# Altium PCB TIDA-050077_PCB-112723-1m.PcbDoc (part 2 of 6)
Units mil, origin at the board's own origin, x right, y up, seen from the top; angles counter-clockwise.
Board outline 3780 x 7750 mil, 16 copper layers (Top Layer, L2-Powet 1, L3-Power 2, L4-Power 3, L5-Power 4, L6-INT 1, L7-INT 2, L8-INT 3, L9-INT 4, L10-INT 5, L11-INT 6, L12-Power 5, L13-Power 6, L14-Power 7, L15-Power 8, Bottom Layer), stack 121.442 mil thick; 381 components, 136 nets, 958 pads, 3470 vias.
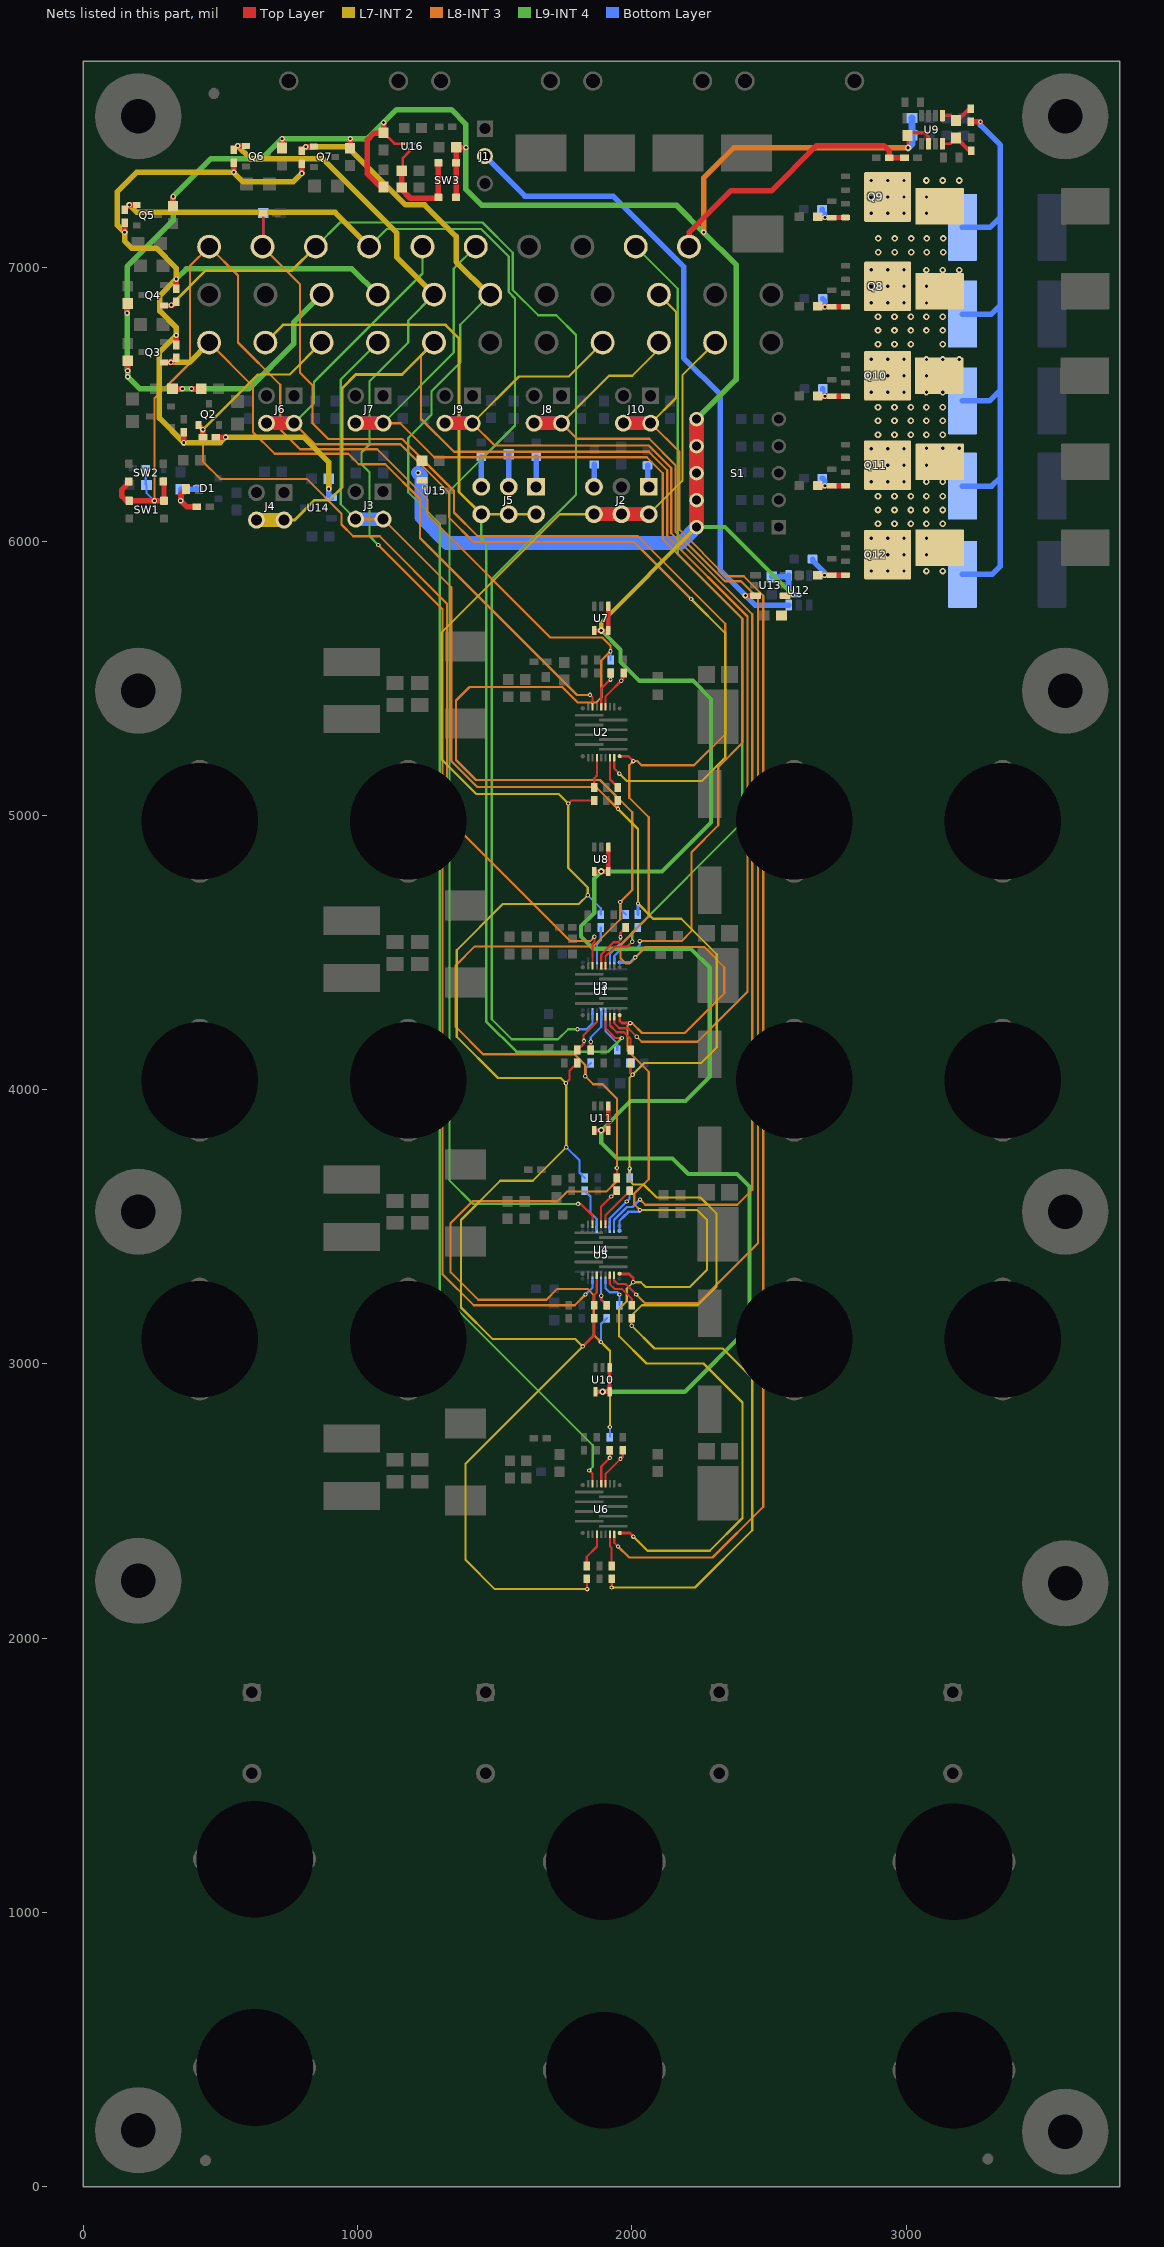
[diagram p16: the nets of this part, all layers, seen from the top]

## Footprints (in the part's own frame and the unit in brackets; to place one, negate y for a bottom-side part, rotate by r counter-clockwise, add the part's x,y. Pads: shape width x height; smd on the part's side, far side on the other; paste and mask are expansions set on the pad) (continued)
SW_76SB05 [mm] "TH, 10-Leads, Body 9.65x14.7mm, Pitch 2.5mm"
  rect 1.35x1.35 hole 0.85: 1(-3.81,5)
  round 1.35 hole 0.85: 2(-3.81,2.5) 3(-3.81,0) 4(-3.81,-2.5) 5(-3.81,-5) 6(3.81,-5) 7(3.81,-2.5) 8(3.81,0) 9(3.81,2.5) 10(3.81,5)
  silkscreen extent -5.25,-7.48 4.95,7.47, body extent -4.95,-7.48 4.95,7.47, height 7.98
Testpoint_Keystone_Compact [mil] "Compact SMT test point"
  rect 185x135 smd: 1(0,0)
  silkscreen extent -110,-80 110,80, body extent -75,-56 75,56, height 91
TI_Stacked_Overlay_Small [mil]
  silkscreen extent -418,-98 418,98
WEEE_Minimum [mil] "WEEElie bin"
  silkscreen extent -95,-172 99,104
Wurth_60900213621 [mil] "Shunt, 2.54mm, Blue"
  round 1 on Mech3: 0(0,0)
  body extent -98,-48 98,48, height 338
YZP0008ADAD [mm] "BGA, 8-Leads, Body 1.9x0.9mm, Pitch 0.5mm"
  round 0.23 smd paste+0 mask+0: A1(-0.25,0.75) A2(0.25,0.75) B1(-0.25,0.25) B2(0.25,0.25) C1(-0.25,-0.25) C2(0.25,-0.25) D1(-0.25,-0.75) D2(0.25,-0.75)
  silkscreen extent -0.6,-1.1 0.6,1.1, body extent -0.46,-0.96 0.46,0.96, height 0.51

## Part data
C1 C2 C4 C5 C8 C9 C15 C16: library part CMP-0006802-4, "CAP, CERM, 0.1 uF, 50 V, +/- 10%, X7R, 0603", Cap_Case=0603, Manufacturer=AVX, Supplier Part Number 1=478-5052-1-ND, TempCo=X7R, Tolerance_%=10%, Value1=Unknown, Value2=50V, ValueDisplayed=0.1uF
C3: library part CMP-0006410-2, "CAP, CERM, 100 pF, 50 V, +/- 5%, C0G/NP0, 0402", Cap_Case=0402, Manufacturer=MuRata, Supplier Part Number 1=81-GRM1555C1H101JA1D, TempCo=C0G/NP0, Tolerance_%=5%, Value1=Unknown, Value2=50V, ValueDisplayed=100pF
C6 C7: library part CMP-0007139-4, "CAP, CERM, 1 uF, 25 V, +/- 10%, X7R, AEC-Q200 Grade 1, 0603", Cap_Case=0603, Manufacturer=MuRata, Supplier Part Number 1=490-10673-1-ND, TempCo=X7R, Tolerance_%=10%, Value1=Unknown, Value2=25V, ValueDisplayed=1uF
C10 C11 C12 C13 C14 C18: library part CMP-0006822-4, "CAP, CERM, 100 pF, 50 V, +/- 5%, C0G/NP0, 0603", Cap_Case=0603, Manufacturer="Wurth Elektronik", TempCo=C0G/NP0, Tolerance_%=5%, Value1=Unknown, Value2=50V, ValueDisplayed=100pF
C17: library part CMP-0085536-1, "CAP, CERM, 0.1 µF, 16 V,+/- 10%, X7R, 0603", Cap_Case=0603, Manufacturer="Samsung Electro-Mechanics", TempCo=X7R, Tolerance_%=10%, Value2=16V, ValueDisplayed=0.1µF
C19 C21 C23 C49 C53 C57 C61 C65: library part CMP-0007052-1, "CAP, CERM, 1 uF, 35 V, +/- 10%, X7R, 0603", Cap_Case=0603, Manufacturer=TDK, Supplier Part Number 1=445-7414-1-ND, TempCo=X7R, Tolerance_%=10%, Value1=Unknown, Value2=35V, ValueDisplayed=1uF
C20 C22 C50 C54 C58 C62 C66 CT1: library part CMP-0079602-1, "CAP, CERM, 0.1 µF, 50 V,+/- 10%, X7R, AEC-Q200 Grade 1, 0603", Cap_Case=0603, Manufacturer=Kemet, Supplier Part Number 1=399-6856-1-ND, TempCo=X7R, Tolerance_%=10%, Value2=50V, ValueDisplayed=0.1µF
C24 C51 C55 C59 C63 C67: library part CMP-0007356-5, "CAP, CERM, 2.2 uF, 35 V, +/- 10%, X5R, 0603", Cap_Case=0603, Manufacturer=MuRata, Supplier Part Number 1=490-7204-6-ND, TempCo=X5R, Tolerance_%=10%, Value1=Unknown, Value2=35V, ValueDisplayed=2.2uF
C25 C52 C56 C60 C64 C68: library part CMP-0075366-1, "CAP, CERM, 2.2 µF, 25 V,+/- 10%, X7S, 0603", Cap_Case=0603, Manufacturer=MuRata, Supplier Part Number 1=490-12732-1-ND, TempCo=X7S, Tolerance_%=10%, Value2=25V, ValueDisplayed=2.2µF
C26: library part CMP-0007173-1, "CAP, CERM, 1000 pF, 50 V, +/- 5%, C0G/NP0, 0603", Cap_Case=0603, Manufacturer=MuRata, Supplier Part Number 1=490-1451-1-ND, TempCo=C0G/NP0, Tolerance_%=5%, Value1=Unknown, Value2=50V, ValueDisplayed=1000pF
C27: library part CMP-0095698-1, "Cap Ceramic 0.047uF 25V X7R 5% SMD 0603 125°C Paper T/R", Digikey Part Number=399-C0603C473J3RAC7867CT-ND, Manufacturer=KEMET, Mouser Part Number=80-C0603C473J3R, Operating Temperature Range="-55°C to +125°C", TempCo=15%, Temperature Characteristic=X7R, Tolerance_%=5%, ValueDisplayed=0.047uF
C28 CD1: library part CMP-0095694-1, "Cap Ceramic 22000pF 50V X7R 10% Pad SMD 0603 Soft Termination +125°C Automotive T/R", Manufacturer=Murata, Operating Temperature Range="-55°C to +125°C", TempCo=15%, Temperature Characteristic=X7R, Tolerance_%=10%, ValueDisplayed=22000pF
C29 CD2: library part CMP-0095695-1, "Cap Ceramic 33000pF 50V X7R 10% Pad SMD 0603 Soft Termination +125°C Automotive T/R", Manufacturer=Murata, Operating Temperature Range="-55°C to +125°C", TempCo=15%, Temperature Characteristic=X7R, Tolerance_%=10%, ValueDisplayed=33000pF
C30 CD3: library part CMP-0007210-3, "CAP, CERM, 3300 pF, 50 V, +/- 5%, C0G/NP0, 0603", Cap_Case=0603, Manufacturer=MuRata, Supplier Part Number 1=GRM1885C1H332JA01D-ND, TempCo=C0G/NP0, Tolerance_%=5%, Value1=Unknown, Value2=50V, ValueDisplayed=3300pF
C31 C32 C33 C40 C41 C42: library part CMP-0009426-2, "CAP, CERM, 47 uF, 25 V, +/- 20%, X7S, 6x5x5mm", Cap_Case=2220, Manufacturer=TDK, Supplier Part Number 1=445-7106-1-ND, TempCo=X7S, Tolerance_%=20%, Value1=Unknown, Value2=25V, ValueDisplayed=47uF
C34 C35 C36 C37 C38 C39 C43 C44 C45 C46 C47 C48: library part CMP-0007828-2, "CAP, CERM, 10 uF, 25 V, +/- 10%, X5R, 0805", Cap_Case=0805, Manufacturer=TDK, Supplier Part Number 1=445-5984-1-ND, TempCo=X5R, Tolerance_%=10%, Value1=Unknown, Value2=25V, ValueDisplayed=10uF
CF1: library part CMP-0006309-1, "CAP, CERM, 1000 pF, 50 V, +/- 5%, C0G/NP0, AEC-Q200 Grade 1, 0402", Cap_Case=0402, Manufacturer=TDK, Supplier Part Number 1=445-6885-1-ND, TempCo=C0G/NP0, Tolerance_%=5%, Value1=Unknown, Value2=50V, ValueDisplayed=1000pF
CM1: library part CMP-0095693-1, "AgPd Termination Conductive Glue Mounting Chip Multilayer Ceramic Capacitors for Automotive 22pF with 5% as tolerance, 50V X8G 30ppm/°C, 0603 Package", Manufacturer=Murata, Operating Temperature Range="-55°C to +150°C", TempCo=30ppm/°C, Temperature Characteristic=X8G, Tolerance_%=0.05%, ValueDisplayed=22pF
CO1 CO2 CO3: library part CMP-0010865-1, "CAP, AL, 470 uF, 25 V, +/- 20%, SMD", Cap_Case=JA0, Manufacturer=Chemi-Con, Supplier Part Number 1=565-2224-1-ND, Tolerance_%=20%, Value1=Unknown, Value2=25V, ValueDisplayed=470uF
CO4 CO5 CO6 CO7: library part CMP-0010371-1, "CAP, AL, 4700 uF, 25 V, +/- 20%, TH", Cap_Case=16x25mm, Manufacturer=Chemi-Con, Tolerance_%=20%, Value1=Unknown, Value2=25V, ValueDisplayed=4700uF
CTEMP1: library part CMP-0006775-4, "CAP, CERM, 22 pF, 50 V, +/- 5%, C0G/NP0, 0603", Cap_Case=0603, Manufacturer=AVX, Supplier Part Number 1=478-1167-1-ND, TempCo=C0G/NP0, Tolerance_%=5%, Value1="0.259 ohm", Value2=50V, ValueDisplayed=22pF
D1: library part CMP-0095562-1, "Zener Diode 4.7 V 250 mW ±1% Surface Mount TO-236AB", Digikey Part Number=1727-5316-1-ND, Forward Current=200mA, Manufacturer=Nexperia, Max Reverse Leakage Current=3uA, Mouser Part Number=771-BZX84-A4V7,215, Operating Temperature Range="-65°C to +150°C", Power_W=250mW
D2 D3 D4 D5 D6 D7: library part CMP-0005677-4, "Diode, TVS, Uni, 12 V, 19.9 Vc, SMC", Manufacturer=Littelfuse, Value1=5000W
D8 D9 D10 D11 D12 D13: library part CMP-0098305-1, "Diode Schottky 45V 10A Surface Mount CFP15B", Digikey Part Number=1727-PMEG045V100EPE-QZCT-ND, Forward Current=14A, Manufacturer=Nexperia, Max Surge Forward Current=300A, Mouser Part Number=771-PMEG045V100EPEQZ, Operating Temperature Range="to +175°C", Peak Reverse Current=150uA, ValueDisplayed=1140pF
DG1: library part CMP-0002980-2, "LED, Green, SMD", Color=Green, Manufacturer=OSRAM, Supplier Part Number 1=475-1410-1-ND, Value1=W, Value2=2.2V
DR1 DR2 DR3 DR4 DR5 DR6: library part CMP-0082438-1, "LED, Red, SMD", Color=Red, Manufacturer=OSRAM, Supplier Part Number 1=475-1278-1-ND, Value1=W, Value2=2V
FID5 FID5_1 FID5_2 FID6 FID6_1 FID6_2: library part CMP-0077181-1, "Fiducial mark.  There is nothing to buy or mount.", Manufacturer=N/A
G1 G2 G3 G4: library part CMP-0075110-1, "1mm Uninsulated Shorting Plug, 10.16mm spacing, TH", Manufacturer=Harwin, Supplier Part Number 1=952-1873-ND
H1 H2 H3 H4 H9 H10 H11 H12 H17 H18: library part CMP-0003617-1, "Machine Screw, Round, #4-40 x 1/4, Nylon, Philips panhead", Manufacturer="B&F Fastener Supply", Supplier Part Number 1=H542-ND
H5 H6 H7 H8 H13 H14 H15 H16 H19 H20: library part CMP-0003610-1, "Standoff, Hex, 0.5\"L #4-40 Nylon", Manufacturer=Keystone, Supplier Part Number 1=36-1902C-ND
J1: library part CMP-0002338-1, "Header, 100mil, 3x1, Tin, TH", Color=Black, Current_A=3A, Manufacturer="Sullins Connector Solutions", PartNumber=PEC03SAAN, Supplier Part Number 1=S1012E-03-ND, Voltage_V=1.8kV
J2 J5: library part CMP-0054552-1, "Header, 100mil, 3x2, Tin, TH", Color=Black, Current_A=3A, Manufacturer="Sullins Connector Solutions", Supplier Part Number 1=S2012E-03-ND, Voltage_V=1.8kV
J3 J4 J6 J7 J8 J9 J10: library part CMP-0095565-1, Current_A=3A, Digikey Part Number=S2022E-02-ND, Manufacturer="Sullins Connector Solutions", Operating Temperature Range="-65°C to +125°C"
L1: library part CMP-0074769-1
L2: library part CMP-0074847-1, "FCC_disclaimer"
L3: library part CMP-0074837-1, "IEC 61010-1 Hot Surface Warning"
L4: library part CMP-0074844-1
Logo1: library part CMP-0074838-1, "Texas Instrument Corporate Signature"
Q1 Q2 Q3 Q4 Q5 Q6 Q7: library part CMP-0095692-1, "N-Channel 30 V 3.16A (Ta) 750mW (Ta) Surface Mount SOT-23-3 (TO-236)", Digikey Part Number=SI2306BDS-T1-GE3CT-ND, Drain To Source Breakdown Voltage=30V, Input Capacitace At Vds="305pF @ 15V", Manufacturer="Vishay Siliconix", Mouser Part Number=781-SI2306BDS-T1-GE3, Operating Temperature Range="-55°C to +150°C", Power_W=1.25W, Pulse Drain Current=20A, Typ Forward Diode Voltage=0.8V
Q8 Q9 Q10 Q11 Q12: library part CMP-0077216-2, "MOSFET, N-CH, 40 V, 42 A, DNK0008A (VSON-CLIP-8)", Alternate Manufacturer=None, Manufacturer="Texas Instruments", Supplier Part Number 1=CSD18510Q5B-ND, Value1="0.0016 ohm", Value2="118 nC"
QGND1 QGND2 QGND3 QGND4 QGND5: library part CMP-0055153-1, "Test Point, Compact, SMT", Manufacturer=Keystone, Supplier Part Number 1=36-5016TR-ND
R1 R2 R3 R4 R7 R8 R9: library part CMP-0025924-5, "RES, 470, 5%, 0.1 W, 0603", Manufacturer=Yageo, Power_W=100mW, Supplier Part Number 1=311-470GRCT-ND, TempCo="100 ppm/C", Tolerance_%=5%, Value2=0.1W, Value_Code=470R, ValueDisplayed=470
R5 R6 R10 R11 R12 R43 R44 R47 R50 R55 R60 R63 R65 R68 R70 R73 R75 R78 R80: library part CMP-0078669-1, "RES, 10.0 k, 1%, 0.063 W, 0402", Manufacturer="Yageo America", Power_W=63mW, Supplier Part Number 1=311-10.0KLRCT-ND, TempCo="100 ppm/C", Tolerance_%=1%, Value2=0.063W, Value_Code=10k0, ValueDisplayed=10.0k
R13 R14: library part CMP-0022746-5, "RES, 10.0 k, 1%, 0.1 W, 0603", Manufacturer=Yageo, Power_W=100mW, Supplier Part Number 1=311-10.0KHRCT-ND, TempCo="100 ppm/C", Tolerance_%=1%, Value2=0.1W, Value_Code=10k0, ValueDisplayed=10.0k
R15 R16: library part CMP-0097819-1, "0 Ohms ±1% Chip Resistor 0603 (1608 Metric) Thick Film", Digikey Part Number=2997-CR160000FTR-ND, Manufacturer="Meritek Electronics", Max Current=2A, Operating Temperature Range="-55°C to +155°C", Power_W=100mW, Tolerance_%=1%
R17: library part CMP-0078210-2, "RES, 330 k, 1%, 0.063 W, AEC-Q200 Grade 0, 0402", Manufacturer=Vishay-Dale, Power_W=63mW, Supplier Part Number 1=541-330KLCT-ND, TempCo="100 ppm/C", Tolerance_%=1%, Value2=0.063W, Value_Code=330k
R18 R19 R20 R21 R22 R33 R34 R35 R36 R37 R41 R59 R64 R69 R74 R79: library part CMP-0095691-1, "Res General Purpose Thick Film 0603 10 Ohm 5% 1/10W ±200ppm/°C Molded SMD Paper T/R", Digikey Part Number=311-10GRCT-ND, Manufacturer=Yageo, Mouser Part Number=603-RC0603JR-0710RL, Operating Temperature Range="-55°C to +155°C", Power_W=100mW, TempCo=200ppm/°C, Tolerance_%=5%
R23 R24 R25 R26 R27: library part CMP-0095896-1, "510 mOhms ±5% 5W Chip Resistor 5329 (13573 Metric), J-Lead Flame Retardant Coating, Safety Wirewound", Digikey Part Number=A103641CT-ND, Manufacturer="TE Connectivity", Mouser Part Number=571-SMW51R0JT, Operating Temperature Range="-55°C to +200°C", Power_W=5W, TempCo=200ppm/°C, Tolerance_%=5%
R28 R29 R30 R31 R32: library part CMP-0091489-1, "1 mOhms ±1% 8W Chip Resistor 3920 (1052 Metric) Current Sense, Moisture Resistant Metal Element", Digikey Part Number=CSS2H-3920R-1L00FCT-ND, Manufacturer=Bourns, Mouser Part Number=652-CSS2H3920R1L00F, Operating Temperature Range="-55°C to +170°C", Power_W=8W, TempCo=100ppm/°C, Tolerance_%=1%
R38 R39 R40: library part CMP-0025886-5, "RES, 10 k, 5%, 0.1 W, 0603", Manufacturer=Yageo, Power_W=100mW, Supplier Part Number 1=311-10KGRCT-ND, TempCo="100 ppm/C", Tolerance_%=5%, Value2=0.1W, Value_Code=10k0, ValueDisplayed=10k
R42: library part CMP-0026859-1, "RES, 1.0 M, 5%, 0.063 W, 0402", Manufacturer=Vishay-Dale, Power_W=63mW, Supplier Part Number 1=541-1.0MJCT-ND, TempCo="200 ppm/C", Tolerance_%=5%, Value2=0.063W, Value_Code=1M00, ValueDisplayed=1.0M
R45: library part CMP-0024214-3, "RES, 40.2 k, 0.1%, 0.1 W, 0603", Manufacturer="Yageo America", Power_W=100mW, TempCo="25 ppm/C", Tolerance_%=0.1%, Value2=0.1W, Value_Code=40k2, ValueDisplayed=40.2k
R46: library part CMP-0021998-4, "RES, 10.0 k, 1%, 0.1 W, AEC-Q200 Grade 0, 0603", Manufacturer=Vishay-Dale, Power_W=100mW, Supplier Part Number 1=541-10.0KHCT-ND, TempCo="100 ppm/C", Tolerance_%=1%, Value2=0.1W, Value_Code=10k0, ValueDisplayed=10.0k
R48: library part CMP-0022770-4, "RES, 121 k, 1%, 0.1 W, 0603", Manufacturer=Yageo, Power_W=100mW, Supplier Part Number 1=311-121KHRCT-ND, TempCo="100 ppm/C", Tolerance_%=1%, Value2=0.1W, Value_Code=121k
R49: library part CMP-0025950-1, "RES, 100 k, 1%, 0.063 W, 0402", Manufacturer=Vishay-Dale, Power_W=63mW, Supplier Part Number 1=541-100KLCT-ND, TempCo="100 ppm/C", Tolerance_%=1%, Value2=0.063W, Value_Code=100k
r51: library part CMP-0023795-3, "RES, 167, 0.1%, 0.1 W, 0603", Manufacturer="Yageo America", Power_W=100mW, TempCo="25 ppm/C", Tolerance_%=0.1%, Value2=0.1W, Value_Code=167R, ValueDisplayed=167
R52: library part CMP-0021998-2, "RES, 10.0 k, 1%, 0.1 W, 0603", Manufacturer=Vishay-Dale, Power_W=100mW, Supplier Part Number 1=541-10.0KHCT-ND, TempCo="100 ppm/C", Tolerance_%=1%, Value2=0.1W, Value_Code=10k0, ValueDisplayed=10.0k
R53: library part CMP-0022204-1, "RES, 20.0 k, 1%, 0.1 W, 0603", Manufacturer=Vishay-Dale, Power_W=100mW, Supplier Part Number 1=541-20.0KHCT-ND, TempCo="100 ppm/C", Tolerance_%=1%, Value2=0.1W, Value_Code=20k0, ValueDisplayed=20.0k
R54: library part CMP-0023987-2, "RES, 249, 0.1%, 0.1 W, 0603", Manufacturer="Yageo America", Power_W=100mW, TempCo="25 ppm/C", Tolerance_%=0.1%, Value2=0.1W, Value_Code=249R, ValueDisplayed=249
R56: library part CMP-0022447-1, "RES, 49.9 k, 1%, 0.1 W, 0603", Manufacturer=Vishay-Dale, Power_W=100mW, Supplier Part Number 1=541-49.9KHCT-ND, TempCo="100 ppm/C", Tolerance_%=1%, Value2=0.1W, Value_Code=49k9, ValueDisplayed=49.9k
R57: library part CMP-0021990-4, "RES, 100 k, 1%, 0.1 W, AEC-Q200 Grade 0, 0603", Manufacturer=Vishay-Dale, Power_W=100mW, Supplier Part Number 1=541-100KHCT-ND, TempCo="100 ppm/C", Tolerance_%=1%, Value2=0.1W, Value_Code=100k
R58: library part CMP-0022200-1, "RES, 200 k, 1%, 0.1 W, 0603", Manufacturer=Vishay-Dale, Power_W=100mW, Supplier Part Number 1=541-200KHCT-ND, TempCo="100 ppm/C", Tolerance_%=1%, Value2=0.1W, Value_Code=200k
R61 R66 R71 R76 R81 RL1: library part CMP-0024153-1, "RES, 365, 0.1%, 0.1 W, 0603", Manufacturer="Yageo America", Power_W=100mW, TempCo="25 ppm/C", Tolerance_%=0.1%, Value2=0.1W, Value_Code=365R, ValueDisplayed=365
R62 R67 R72 R77 R82 RL2: library part CMP-0024259-2, "RES, 464, 0.1%, 0.1 W, 0603", Manufacturer="Yageo America", Power_W=100mW, TempCo="25 ppm/C", Tolerance_%=0.1%, Value2=0.1W, Value_Code=464R, ValueDisplayed=464
RM1 RM2 RM3 RM4 RM5: library part CMP-0026822-2, "RES, 0, 5%, 0.063 W, 0402", Manufacturer=Vishay-Dale, Power_W=63mW, Supplier Part Number 1=541-0.0JCT-ND, TempCo="200 ppm/C", Tolerance_%=5%, Value2=0.063W, Value_Code=0000, ValueDisplayed=0
RZ1 RZ2 RZ3 RZ4 RZ5 RZ6 RZ7 RZ8 RZ9 RZ10 RZ11 RZ12 RZ13 RZ14 RZ15 RZ16 RZ17 RZ18 RZ19 RZ20 RZ21 RZ22 RZ23 RZ24 RZ25 RZ26 RZ27 RZ28 RZ29 RZ30 RZ31 RZ32 RZ33 RZ34 RZ35 RZ36 RZ37 RZ38 RZ39 RZ40 RZ41 RZ42 RZ43 RZ44 RZ45 RZ46: library part CMP-0026822-3, "RES, 0, 5%, 0.063 W, AEC-Q200 Grade 0, 0402", Manufacturer=Vishay-Dale, Power_W=63mW, Supplier Part Number 1=541-0.0JCT-ND, TempCo="200 ppm/C", Tolerance_%=5%, Value2=0.063W, Value_Code=0000, ValueDisplayed=0
S1: library part CMP-0002222-1, "Switch, SPST 5Pos, Rocker, TH", CurrentRating_mA=150A, Manufacturer=Grayhill, Supplier Part Number 1=GH7171-ND
SH1 SH2 SH3 SH4 SH5 SH6 SH7 SH8 SH9: library part CMP-0003763-2, "Shunt, 2.54mm, Gold, Blue", Manufacturer="Wurth Elektronik"
SW1 SW2 SW3: library part CMP-0087766-1, "Tactile Switch SPST-NO Top Actuated Surface Mount", Manufacturer="C&K Components"
T1 T2 T3 T4 T14 T15 T16 T17: library part CMP-0055005-1, "Connector, Receptacle, Pin, TH", Manufacturer=Mill-Max, PartNumber=0300-2-15-01-47-01-10-0, Supplier Part Number 1=0300-215014701100-ND
T5 T6 T7 T8 T9 T10 T11 T12 T13: library part CMP-0093713-2, "1/0 AWG High AMP PCB Wire Lugs 1/0-8 AWG", Current_A=150A, Manufacturer="INTERNATIONAL HYDRAULICS", Operating Temperature Range=to
TP1 TP2 TP3 TP4 TP5 TP6 TP7 TP8 TP9 TP10 TP11 TP12 TP13 TP14 TP16 TP17 TP18 TP19 TP20 TP21 TP22 TP27 TP29 TP30 TP31 TP32 TP33 TP34 TP35 TP36 TP39: library part CMP-0055158-1, "Test Point, Multipurpose, Green, TH", Color=Green, Manufacturer=Keystone, PartNumber=5126, Supplier Part Number 1=36-5126-ND
TP15: library part CMP-0055148-1, "Test Point, Multipurpose, Black, TH", Color=Black, Manufacturer=Keystone, PartNumber=5011, Supplier Part Number 1=36-5011-ND
U1 U2 U3 U4 U5 U6: library part CMP-0091052-1, Manufacturer="Texas Instruments", Operating Temperature Range=to
U7 U8 U10 U11: library part CMP-0073328-2, "1.5V, Multi-Gain Analog Temperature Sensor with Class-AB Output, 5-pin SC-70, Pb-Free", Manufacturer="Texas Instruments", PackageTopMarking=22B*XTT, PowerWise=Y
U9: library part CMP-0093647-2, "-4-V to 110V, Bidirectional, Ultra-Precise Current Sense Amplifier With Enhanced PWM Rejection", Input Bias Current=40uA, Input Offset Voltage=0.002mV, Manufacturer="Texas Instruments", Max Supply Voltage=20V, Min Supply Voltage=2.7V, Nominal Supply Current=2.5mA, Operating Temperature Range="-40°C to +125°C", Voltage Gain=0.01V/mV
U12 U13: library part CMP-0077683-1, "Single-Channel High-Speed Low-Side Gate Driver with 5V Negative Input Voltage Handling Ability, DBV0006A (SOT-23-6)", Alternate Manufacturer="Texas Instruments"
U14: library part CMP-0074893-1, "100-mA, 30-V, Fixed-Output, Linear-Voltage Regulator, DBZ0003A (SOT-23-3)", Alternate Manufacturer="Texas Instruments", Alternate PartNumber=TLV76033DBZT
U15: library part CMP-0074892-1, "100-mA, 30-V, Fixed-Output, Linear-Voltage Regulator, DBZ0003A (SOT-23-3)", Alternate Manufacturer="Texas Instruments", Alternate PartNumber=TLV76050DBZT
U16: library part CMP-0050969-2, "Single Retriggerable Monostable Multivibrator with Schmitt-Trigger Inputs, YZP0008ADAD, LARGE T&R", F @ Nom Voltage(Max)(Mhz)=150, Generic Part Number=SN74LVC1G123, ICC @ Nom Voltage(Max)(mA)=0.02, Manufacturer="Texas Instruments", Operating Temperature Range(C)="-40 to 125,-40 to 85", Rating=Catalog, tpd @ Nom Voltage(Max)(ns)=34,11,8,5.5, Voltage(Nom)(V)=1.8,2.5,3.3,5
ZZ1: library part CMP-0003616-3
ZZ2: library part CMP-0077236-1
ZZ3: library part CMP-0077237-1
ZZ4: library part CMP-0077238-1

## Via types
v1: diameter 24, hole 12, Top Layer to Bottom Layer, 2618 vias
v2: diameter 20, hole 10, Top Layer to Bottom Layer, 508 vias
v3: diameter 16, hole 8, Top Layer to Bottom Layer, tented both sides, 135 vias
v4: diameter 24, hole 12.1, Top Layer to Bottom Layer, 125 vias
v5: diameter 20, hole 10, Top Layer to Bottom Layer, tented both sides, 84 vias

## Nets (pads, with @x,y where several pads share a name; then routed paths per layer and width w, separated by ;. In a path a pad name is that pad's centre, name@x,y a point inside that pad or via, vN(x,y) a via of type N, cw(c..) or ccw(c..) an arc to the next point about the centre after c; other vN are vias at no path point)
+3P3V: C9.1 R5.1 R6.1 R10.1 R11.1 R12.1 R43.1 R44.1 TP6.1 U14.1 | length 3680.4
  Top Layer w20: v5(150.14,7126.55) R10.1@150.14,7161.81 ; R5.1@338.47,6715.88 v5(338.47,6751.14) ; R6.1@338.47,6920.99 v5(338.47,6956.24) ; v5(366.08,6359.76) R44.1@366.08,6397.65 ; R43.1@483.33,6379.76 v5(518.58,6379.76) ; v5(547.94,7345.53) R11.1@547.94,7380.78 ; v5(795.95,7341.38) R12.1@795.95,7376.63
  L7-INT 2 w20: v5(795.95,7341.38) 765.32,7310.75 582.72,7310.75 v5(547.94,7345.53) 194.4,7345.53 124.28,7275.4 124.28,7152.41 v5(150.14,7126.55) 150.14,7095.02 176.26,7068.9 266,7068.9 338.47,6996.43 v5(338.47,6956.24) 279.28,6897.06 279.28,6839.61 338.47,6780.43 v5(338.47,6751.14) 277.17,6689.84 277.17,6448.67 v5(366.08,6359.76) 498.58,6359.76 v5(518.58,6379.76) 803.42,6379.76 894.7,6288.48 v5(894.7,6190.73)
  L9-INT 4 w20: v5(338.47,6956.24) 375.89,6993.67 979.56,6993.67 TP6.1@1073.73,6899.5
  Bottom Layer w20: C9.1@894.7,6228.15 v5(894.7,6190.73) 894.7,6169.23 U14.1@904.49,6159.45
+5V: C1.2 C6.1 C7.1 C16.1 C17.1 R1.1 R2.1 R3.1 R4.1 R7.1 R8.2 R9.1 R13.2 R14.2 R38.2 R39.2 S1.6 S1.7 S1.8 S1.9 S1.10 SW3.3 SW3.4 TP7.1 U7.1 U7.4 U7.5 U8.1 U8.4 U8.5 U9.6 U10.1 U10.4 U10.5 U11.1 U11.4 U11.5 U12.1 U13.1 U15.1 U16.A2 | length 15574
  Top Layer w10: C17.1@1094.85,7489.48 1134.56,7449.78 U16.A2@1169.36,7449.78
  Top Layer w12: v1(3007.44,7434.49) 3007.44,7476.84 C1.2@3005.07,7479.2 3015.89,7490.02 3067.67,7490.02 3081.83,7475.85 U9.6@3081.83,7449.64
  Top Layer w15: U11.4@1863.04,3851.74 v1(1888.63,3851.74) U11.5@1914.22,3851.74 U11.1@1914.22,3940.33 ; U8.4@1863.04,4795.94 v1(1888.63,4795.94) U8.5@1914.22,4795.94 U8.1@1914.22,4884.52 ; U7.4@1863.04,5674.61 v1(1888.63,5674.61) U7.5@1914.22,5674.61 U7.1@1914.22,5763.19 ; U10.4@1867.8,2898.71 v1(1893.39,2898.71) U10.5@1918.98,2898.71 U10.1@1918.98,2987.29
  Top Layer w20: v5(159.41,6832.11) R1.1@159.41,6867.37 ; v5(161.34,6622.11) R7.1@161.34,6657.37 ; R8.2@326.08,6555.95 v5(361.34,6555.95) ; R2.1@327.5,7221.92 v5(327.5,7257.18) ; v5(394.33,6556.19) R9.1@429.59,6556.19 ; R3.1@724.38,7434.18 v5(724.38,7468.21) ; R4.1@973.31,7432.95 v5(973.31,7468.21) ; R38.2@1094.85,7291.49 1083.78,7291.49 1035.62,7339.64 1035.62,7463.91 1059.85,7488.14 1093.52,7488.14 C17.1@1094.85,7489.48 v5(1094.85,7526.66) ; SW3.3@1359.44,7253.73 1359.44,7421.89 R39.2@1367.11,7429.57 ; R39.2@1359.85,7435.8 v5(1395.11,7435.8)
  Top Layer w50: S1.10@2235.98,6051.59 S1.9@2235.98,6150.01 S1.8@2235.98,6248.44 S1.7@2235.98,6346.86 S1.6@2235.98,6445.29
  L8-INT 3 w20: v5(2261.88,7126.66) 2261.88,7325.11 2371.26,7434.49 v1(3007.44,7434.49)
  L7-INT 2 w15: v1(1888.63,5674.61) 1888.63,5704.25 S1.10@2235.98,6051.59
  L9-INT 4 w15: v1(1888.63,5674.61) 1958.86,5604.38 1958.86,5559.53 2026.92,5491.47 2223.25,5491.47 2289.28,5425.44 2289.28,4974.93 2110.29,4795.94 v1(1888.63,4795.94) 1862.98,4770.28 1862.98,4644.23 1815.22,4596.47 1815.22,4558.78 1860.1,4513.9 2215.14,4513.9 2284.28,4444.76 2284.28,4048.08 2195.1,3958.9 1995.79,3958.9 v1(1888.63,3851.74) 1888.63,3806.21 1945.95,3748.9 2149.01,3748.9 2205.82,3692.09 2384.2,3692.09 2429.28,3647 2429.28,3134.81 2193.18,2898.71 v1(1893.39,2898.71) ; S1.10@2235.98,6051.59 2340.27,6051.59 v3(2587.33,5804.53)
  L9-INT 4 w20: TP7.1@868.73,6899.5 767.98,6798.75 767.98,6720.37 603.8,6556.19 v5(394.33,6556.19) 394.1,6555.95 v5(361.34,6555.95) 205.95,6555.95 v5(162.04,6599.87) 161.34,6600.56 v5(161.34,6622.11) 159.41,6624.04 v5(159.41,6832.11) 159.41,7001.23 327.5,7169.32 v5(327.5,7257.18) 465.72,7395.4 651.56,7395.4 v5(724.38,7468.21) v5(973.31,7468.21) 1036.4,7468.21 v5(1094.85,7526.66) 1142.09,7573.9 1341.84,7573.9 1395.11,7520.63 v5(1395.11,7435.8) 1395.11,7283.07 1453.49,7224.69 2163.86,7224.69 v5(2261.88,7126.66) 2380.01,7008.53 2380.01,6589.32 S1.6@2235.98,6445.29
  Bottom Layer w20: C6.1@2510.54,5870.12 2566.01,5870.12 U12.1@2571.4,5875.52 2571.4,5820.46 v3(2587.33,5804.53) v3(2609.67,5804.53)
  Bottom Layer w25: v1(3007.44,7434.49) 3021.77,7448.82 R13.2@3021.77,7480.73 R14.2@3021.77,7543.4
  Bottom Layer w50: v5(1220.33,6249.5) 1232.13,6237.69 1232.13,6087.29 1325.52,5993.9 2178.29,5993.9 S1.10@2235.98,6051.59 S1.9@2235.98,6150.01 S1.8@2235.98,6248.44 S1.7@2235.98,6346.86 S1.6@2235.98,6445.29
  other v5: 1245.33,6197.5
CSA_IN-: Q8.5 Q8.6 Q8.7 Q8.8 Q8.9@2932.75,6929.56 Q9.5 Q9.6 Q9.7 Q9.8 Q9.9@2932.75,7255.62 Q10.5 Q10.6 Q10.7 Q10.8 Q10.9@2932.75,6603.5 Q11.5 Q11.6 Q11.7 Q11.8 Q11.9@2932.75,6277.43 Q12.5 Q12.6 Q12.7 Q12.8 Q12.9@2932.75,5951.37 R23.1 R24.1 R25.1 R26.1 R27.1 R28.1 R29.1 R30.1 R31.1 R32.1 RZ3.2 | length 2448.1
  Top Layer w20: RZ3.2@3236.8,7529.94 v3(3271.27,7529.94)
  Bottom Layer w20: R31.1@3205.78,5879.5 3313.99,5879.5 3344.04,5909.55 3344.04,6232.49 ; R30.1@3205.78,6200.81 3312.37,6200.81 3344.04,6232.49 ; R29.1@3205.78,6512.12 3303.84,6512.12 3344.04,6552.33 ; R28.1@3205.78,6828.44 3310.75,6828.44 3344.04,6861.73 ; R32.1@3205.78,7144.75 3306.04,7144.75 3344.04,7182.75 ; v3(3271.27,7529.94) 3271.27,7517.52 3344.04,7444.75 3344.04,7182.75 ; 3344.04,6232.49 3344.04,6552.33 ; 3344.04,6552.33 3344.04,6861.73 ; 3344.04,6861.73 3344.04,7182.75
  other v4: 2872.75,5891.37 2932.75,5891.37 2992.75,5891.37 3074.28,5891.37 3134.28,5891.37 2872.75,5951.37 2932.75,5951.37 2992.75,5951.37 3074.28,5951.37 2872.75,6011.37 2932.75,6011.37 2992.75,6011.37 3074.28,6011.37 2897.75,6063.9 2957.75,6063.9 3017.75,6063.9 3074.28,6063.9 3134.28,6063.9 2897.75,6113.9 2957.75,6113.9 3017.75,6113.9 3074.28,6113.9 3134.28,6113.9 2897.75,6163.9 2957.75,6163.9 3017.75,6163.9 3074.28,6163.9 3134.28,6163.9 3074.28,6216.85 3134.28,6216.85 2872.75,6217.43 2932.75,6217.43 2992.75,6217.43 2872.75,6277.43 2932.75,6277.43 2992.75,6277.43 3074.28,6277.43 2872.75,6337.43 2932.75,6337.43 2992.75,6337.43 3074.28,6338.9 3134.28,6338.9 3194.28,6338.9 2897.75,6388.9 2957.75,6388.9 3017.75,6388.9 3074.28,6388.9 3134.28,6388.9 2897.75,6438.9 2957.75,6438.9 3017.75,6438.9 3074.28,6438.9 3134.28,6438.9 2897.75,6488.9 2957.75,6488.9 3017.75,6488.9 3074.28,6488.9 3134.28,6488.9 2872.75,6543.5 2932.75,6543.5 2992.75,6543.5 3074.28,6543.5 3134.28,6543.5 2872.75,6603.5 2932.75,6603.5 2992.75,6603.5 3074.28,6603.5 3074.28,6662.76 3134.28,6662.76 3194.28,6662.76 2872.75,6663.5 2932.75,6663.5 2992.75,6663.5 2897.75,6718.9 2957.75,6718.9 3017.75,6718.9 3134.28,6718.9 2897.75,6768.9 2957.75,6768.9 3017.75,6768.9 3074.28,6768.9 3134.28,6768.9 2897.75,6818.9 2957.75,6818.9 3017.75,6818.9 3074.28,6818.9 3134.28,6818.9 3074.28,6868.9 2872.75,6869.56 2932.75,6869.56 2992.75,6869.56 2872.75,6929.56 2932.75,6929.56 2992.75,6929.56 3074.28,6929.56 3074.28,6988.9 3134.28,6988.9 3194.28,6988.9 2872.75,6989.56 2932.75,6989.56 2992.75,6989.56 2898.8,7054.26 2958.8,7054.26 3018.8,7054.26 3075.33,7054.26 3135.33,7054.26 2898.8,7104.26 2958.8,7104.26 3018.8,7104.26 3075.33,7104.26 3135.33,7104.26 2872.75,7195.62 2932.75,7195.62 2992.75,7195.62 3074.28,7195.62 2872.75,7255.62 2932.75,7255.62 2992.75,7255.62 3074.28,7255.62 2872.75,7315.62 2932.75,7315.62 2992.75,7315.62 3074.28,7315.62 3134.28,7315.62 3194.28,7315.62
DVDT: J2.2 J2.4 J2.6 RZ7.2 RZ14.2 RZ21.2 RZ28.2 RZ35.2 RZ42.2 TP27.1 | length 8331.8
  Top Layer w8: v3(1759.72,4023.9) 1773.07,4037.24 1773.07,4069 RZ7.2@1801.66,4097.6 ; v3(1767.84,5043.9) 1778.69,5054.74 RZ14.2@1862.98,5054.74 ; RZ42.2@1835.88,2216.11 1837.05,2214.95 v3(1837.05,2178.9)
  Top Layer w10: v3(1820.97,3063.9) 1862.98,3105.91 RZ28.2@1862.98,3167.28
  Top Layer w50: J2.6@1862.04,6098.69 J2.4@1962.04,6098.69 J2.2@2062.04,6098.69
  L7-INT 2 w8: v3(1837.05,2178.9) 1500.29,2178.9 1393.92,2285.27 1393.92,2636.85 v3(1820.97,3063.9) 1794.36,3090.51 1492.67,3090.51 1377.22,3205.96 1377.22,3524.81 1520.41,3668.01 1638.77,3668.01 v3(1761.22,3790.46) 1761.22,4022.39 v3(1759.72,4023.9) 1741.23,4042.39 1512.1,4042.39 1361.43,4193.06 1361.43,4509.14 1529.33,4677.05 1806.79,4677.05 v3(1838.98,4709.24) 1838.98,4737.07 1767.84,4808.21 v3(1767.84,5043.9) 1732.84,5078.9 1431.86,5078.9 1306.69,5204.07 1306.69,5667.7 1737.68,6098.69 J2.6@1862.04,6098.69 J2.4@1962.04,6098.69 J2.2@2062.04,6098.69 2184.28,6220.93 2184.28,6605.05 TP27.1@2303.73,6724.5
  Bottom Layer w8: v3(1761.22,3790.46) 1808.87,3742.82 1808.87,3698.18 RZ35.2@1828.77,3678.28 ; v3(1838.98,4709.24) 1886.57,4661.66 RZ21.2@1886.57,4638.63
  Bottom Layer w50: J2.6@1862.04,6098.69 J2.4@1962.04,6098.69 J2.2@2062.04,6098.69
DVDT_0: RZ7.1 U1.4 | length 152.9
  Top Layer w7.87: RZ7.1@1801.66,4144.84 1825.51,4168.69 v3(1825.51,4177.94) 1823.67,4179.78 1823.67,4198.06 1872.89,4247.27 U1.4@1872.89,4266.76
DVDT_1: RZ14.1 U2.4 | length 113.1
  Top Layer w8: RZ14.1@1862.98,5101.98 1862.98,5135.8 1872.89,5145.71 U2.4@1872.89,5210.96
DVDT_2: RZ21.1 U3.4 | length 127.5
  Bottom Layer w8: U3.4@1872.89,4469.52 1872.89,4531.26 1886.57,4544.94 1886.57,4557.5 RZ21.1@1886.57,4591.39
DVDT_3: RZ28.1 U4.4 | length 113.1
  Top Layer w8: RZ28.1@1862.98,3214.52 1862.98,3251.19 1872.19,3260.4 U4.4@1872.19,3323.77
DVDT_4: RZ35.1 U5.4 | length 158.1
  Bottom Layer w8: RZ35.1@1828.77,3631.03 1849.27,3610.53 1849.27,3551.22 1872.19,3528.3 U5.4@1872.19,3490.89
DVDT_5: RZ42.1 U6.4 | length 130.3
  Top Layer w8: RZ42.1@1835.88,2263.36 1835.88,2297.39 1872.89,2334.4 U6.4@1872.89,2378.37
EN: C26.1 R17.2 R42.1 RZ6.2 RZ12.2 RZ19.2 RZ26.2 RZ33.2 RZ40.2 SW1.3 SW1.4 SW2.3 SW2.4 TP21.1 | length 10182.5
  Top Layer w8: RZ26.2@1945.62,3678.28 v3(1945.62,3714.35)
  Top Layer w20: SW2.3@166.03,6217.82 168.04,6215.82 140.59,6188.37 140.59,6164.95 157.97,6147.57 SW1.4@168.04,6147.57 v5(259.02,6147.57) SW1.3@294.02,6147.57 294.02,6215.82 SW2.4@292.01,6217.82
  L8-INT 3 w8: v5(259.02,6147.57) 259.02,6520.27 389.01,6650.26 389.01,7004.77 TP21.1@458.73,7074.5 564.08,6969.14 564.08,6724.86 717.98,6570.96 717.98,6407.71 790,6335.7 1071.54,6335.7 1255.42,6151.82 1255.42,6096.29 1702.81,5648.9 1892.68,5648.9 1922.32,5619.26 v3(1922.32,5598.66) 1888.63,5564.97 1888.63,5430.96 1869.26,5411.59 1803.75,5411.59 1746.44,5468.9 1408.11,5468.9 1358.84,5419.63 1358.84,5202.34 1431.77,5129.41 1884.12,5129.41 2001.66,5011.87 2001.66,4728.63 v3(1957.74,4684.7) 1957.74,4621.36 1859.14,4522.76 1427.33,4522.76 1357.55,4452.98 1357.55,4229.26 1457.18,4129.62 1790.94,4129.62 1830.08,4090.48 v3(1830.08,4048.9) 1858.89,4020.09 1892.95,4020.09 1945.62,3967.42 v3(1945.62,3714.35) 1945.62,3667.18 1906.83,3628.38 1763.77,3628.38 1728.76,3593.37 1418.96,3593.37 1339.28,3513.69 1339.28,3334.56 1439.88,3233.96 1688.62,3233.96 1728.4,3273.75 1838.76,3273.75 1861.44,3251.06 1861.44,3105.84 v3(1887.27,3080.02)
  L7-INT 2 w8: v3(1887.27,3080.02) 1920.13,3047.15 v3(1920.13,2769.91)
  Bottom Layer w8: R17.2@227.64,6265.6 227.64,6207.46 C26.1@229.8,6205.3 229.8,6176.79 v5(259.02,6147.57) 286.44,6147.57 294.02,6155.15 294.02,6219.34 R42.1@292.74,6220.62 ; v3(1830.08,4048.9) v3(1830.08,4048.9) 1829.99,4077.54 RZ19.2@1850.05,4097.6 ; v3(1887.27,3080.02) 1887.27,3145.35 RZ33.2@1909.19,3167.28 ; RZ40.2@1920.13,2733.08 v3(1920.13,2769.91) ; RZ12.2@1922.32,5567.04 v3(1922.32,5598.66) ; v3(1957.74,4684.7) 1957.74,4659.25 RZ6.2@1978.24,4638.75
EN_0: R47.2 RZ6.1 U1.18 | length 230.1
  Top Layer w8: U1.18@1888.63,4451.8 1888.63,4493.34 1933,4537.7 1950.19,4537.7 1958.8,4546.31 v3(1958.8,4556.36) 1958.8,4572.07 R47.2@1978.24,4591.5
  Bottom Layer w8: v3(1958.8,4556.36) 1958.8,4572.07 RZ6.1@1978.24,4591.5
EN_1: R55.2 RZ12.1 U2.18 | length 163.1
  Top Layer w8: U2.18@1888.63,5396 1888.63,5463.37 1920.69,5495.42 v3(1922.32,5495.42) R55.2@1922.32,5519.8
  Bottom Layer w8: v3(1922.32,5495.42) RZ12.1@1922.32,5519.8
EN_2: R63.2 RZ19.1 U3.18 | length 185.6
  Top Layer w7.87: R63.2@1850.05,4144.84 v3(1850.05,4174.86)
  Bottom Layer w7.87: RZ19.1@1850.05,4144.84 v3(1850.05,4174.86) 1850.05,4190.97 1888.63,4229.55 U3.18@1888.63,4284.48
EN_3: R68.2 RZ26.1 U4.18 | length 175.1
  Top Layer w8: U4.18@1887.94,3508.81 1887.94,3573.35 v3(1925.12,3610.53) RZ26.1@1945.62,3631.03
  Bottom Layer w8: v3(1925.12,3610.53) R68.2@1945.62,3631.03
EN_4: R73.2 RZ33.1 U5.18 | length 143
  Top Layer w8: v3(1888.63,3248.84) 1888.63,3235.08 R73.2@1909.19,3214.52
  Bottom Layer w8: U5.18@1887.94,3305.85 1887.94,3249.54 v3(1888.63,3248.84) 1888.63,3235.08 RZ33.1@1909.19,3214.52
EN_5: R78.2 RZ40.1 U6.18 | length 163.9
  Top Layer w8: U6.18@1888.63,2563.41 1888.63,2605.02 1888.69,2605.02 1888.69,2613.39 1888.63,2613.44 1888.63,2625.96 v3(1920.13,2657.46) R78.2@1920.13,2685.83
  Bottom Layer w8: v3(1920.13,2657.46) RZ40.1@1920.13,2685.83
FLTb: Q2.1 R43.2 TP9.1 U1.20 | length 3478.8
  Top Layer w8: U1.20@1857.14,4451.8 1857.14,4532.83 1863.48,4539.16 v3(1863.48,4557.5)
  Top Layer w20: Q2.1@420.09,6423.5 v5(436.08,6407.5) R43.2@436.08,6379.76
  L8-INT 3 w8: v5(436.08,6407.5) 436.08,6290.11 498.77,6227.42 814.28,6227.42 941.03,6100.67 941.03,6060.8 983.73,6018.1 1080.92,6018.1 1326.38,5772.63 1326.38,4991.68 1776.11,4541.95 1847.93,4541.95 v3(1863.48,4557.5)
  L7-INT 2 w8: v5(436.08,6407.5) 636.96,6608.38 752.61,6608.38 TP9.1@868.73,6724.5
FLTb_1: Q3.1 R5.2 TP10.1 U2.20 | length 2370
  Top Layer w8: v3(1847.7,5439.74) 1857.14,5430.29 U2.20@1857.14,5396
  Top Layer w20: Q3.1@293.95,6652.26 v5(319.34,6652.26) 322.09,6652.26 R5.2@338.47,6668.64
  L8-INT 3 w8: TP10.1@458.73,6724.5 618.21,6565.02 618.21,6398.38 697.69,6318.9 966.04,6318.9 1004.4,6280.54 1100.56,6280.54 1227.27,6153.82 1227.27,6012.23 1799.77,5439.74 v3(1847.7,5439.74)
  L7-INT 2 w20: v5(319.34,6652.26) 386.49,6652.26 TP10.1@458.73,6724.5
FLTb_2: Q4.1 R6.2 TP11.1 U3.20 | length 4986.6
  Top Layer w20: Q4.1@293.95,6859.76 324.49,6859.76 R6.2@338.47,6873.74
  L7-INT 2 w10: v5(320.58,6861.37) 445.85,6986.65 759.77,6986.65 TP11.1@847.62,7074.5
  L9-INT 4 w8: TP11.1@847.62,7074.5 935.5,7162.38 1455.85,7162.38 1566.05,7052.18 1566.05,6916.14 1658.29,6823.9 1724.28,6823.9 1796.33,6751.85 1796.33,6169.23 1489.28,5862.18 1489.28,4256.8 1562.35,4183.73 1730.84,4183.73 1767.8,4220.69 v3(1801.84,4220.69)
  Bottom Layer w8: v3(1801.84,4220.69) 1834.42,4220.69 1857.14,4243.41 U3.20@1857.14,4284.48
FLTb_3: Q5.1 R10.2 TP12.1 U4.20 | length 5651.3
  Top Layer w8: v3(1803.99,3583.55) 1814.18,3583.55 1856.44,3541.29 U4.20@1856.44,3508.81
  Top Layer w20: R10.2@150.14,7209.05 167.87,7226.77 Q5.1@194.66,7226.77
  L7-INT 2 w20: v5(167.87,7226.42) 195.39,7198.9 917.66,7198.9 TP12.1@1042.06,7074.5
  L9-INT 4 w8: TP12.1@1042.06,7074.5 1106.46,7138.9 1450.74,7138.9 1551,7038.64 1551,6908.72 1574.28,6885.45 1574.28,6422.1 1334.77,6182.59 1334.77,3669.68 1420.9,3583.55 v3(1803.99,3583.55)
FLTb_4: Q6.1 R11.2 TP13.1 U5.20 | length 5494.8
  Top Layer w20: R11.2@547.94,7428.03 561.74,7441.83 v5(562.68,7441.83) Q6.1@592.46,7441.83
  L8-INT 3 w8: v3(1075.67,5986.44) 1309.97,5752.14 1309.97,3327.4 1423.47,3213.9 1791.97,3213.9 v3(1831.28,3253.21)
  L7-INT 2 w20: v5(562.68,7441.83) 609.11,7395.4 871.71,7395.4 1141.97,7125.13 1141.97,7036.25 TP13.1@1278.73,6899.5
  L9-INT 4 w8: v3(1075.67,5986.44) 1043.21,6018.9 1043.21,6251.97 1014.28,6280.9 1014.28,6323.9 1043.21,6352.82 1043.21,6583.38 1184.6,6724.77 1184.6,6805.37 TP13.1@1278.73,6899.5
  Bottom Layer w8: v3(1831.28,3253.21) 1856.44,3278.37 U5.20@1856.44,3305.85
FLTb_5: Q7.1 R12.2 TP14.1 U6.20 | length 5750.4
  Top Layer w8: v3(1844.34,2611.63) 1857.14,2598.83 U6.20@1857.14,2563.41
  Top Layer w20: R12.2@795.95,7423.88 811.03,7438.96 Q7.1@840.47,7438.96
  L7-INT 2 w20: v5(811.35,7438.23) 963.46,7438.23 1175.26,7226.42 1244.54,7226.42 1359.28,7111.68 1359.28,7018.9 1478.68,6899.5 TP14.1@1483.73,6899.5
  L9-INT 4 w8: TP14.1@1483.73,6899.5 1374.28,6790.05 1374.28,6651.97 1269.28,6546.97 1269.28,6461.06 1184.6,6376.38 1184.6,6178.87 1299.28,6064.19 1299.28,3261.96 1857.82,2703.42 1857.82,2625.11 v3(1844.34,2611.63)
GATE1: C10.2 Q8.4 R18.2 R33.2 | length 136.4
  Top Layer w20: R33.2@2677.79,6856.72 2679.95,6854.56 v5(2704.28,6854.56) Q8.4@2779.21,6854.56
  Bottom Layer w20: R18.2@2695.75,6885.07 2704.28,6876.54 v5(2704.28,6854.56)
GATE2: C11.2 Q9.4 R19.2 R34.2 | length 136.8
  Top Layer w20: R34.2@2677.79,7183.5 2680.67,7180.62 v5(2704.28,7180.62) Q9.4@2779.21,7180.62
  Bottom Layer w20: R19.2@2693.78,7210.5 2693.78,7201.28 2704.28,7190.78 v5(2704.28,7180.62)
GATE3: C12.2 Q10.4 R20.2 R35.2 | length 133.8
  Top Layer w20: R35.2@2677.79,6529.93 2679.23,6528.5 v5(2704.28,6528.5) C12.2@2728.33,6528.5 Q10.4@2779.21,6528.5
  Bottom Layer w20: R20.2@2696.56,6557.06 2696.56,6536.22 v5(2704.28,6528.5)
GATE4: C13.2 Q11.4 R21.2 R36.2 | length 133.3
  Top Layer w20: R36.2@2677.79,6203.15 2678.51,6202.43 v5(2704.28,6202.43) Q11.4@2779.21,6202.43
  Bottom Layer w20: R21.2@2694.66,6230.06 2704.28,6220.43 v5(2704.28,6202.43)
GATE5: C14.2 Q12.4 R22.2 R37.2 | length 178.4
  Top Layer w20: R37.2@2677.79,5876.37 v5(2703.06,5876.37) C14.2@2728.33,5876.37 Q12.4@2779.21,5876.37
  Bottom Layer w20: R22.2@2658.99,5935.11 2658.99,5929.95 2703.06,5885.88 v5(2703.06,5876.37)
GD_IN: J1.2 U12.6 U13.6 | length 2396.7
  Top Layer w20: v5(2414.33,5802.1) U13.6@2455.19,5802.1
  Bottom Layer w20: J1.2@1464.28,7404.41 1609.79,7258.9 1931.64,7258.9 2189.28,7001.26 2189.28,6668.84 2321.94,6536.17 2321.94,5894.48 v5(2414.33,5802.1) 2449.18,5767.25 U12.6@2571.4,5767.25
ILIM: J4.2 J4.4 TP31.1 U1.8 | length 5136.8
  Top Layer w8: U1.8@1935.88,4266.76 1935.88,4242.89 1954.34,4224.42 1986.66,4224.42 v3(2018.14,4192.94)
  L8-INT 3 w8: TP31.1@1278.73,6724.5 1231.48,6677.24 1231.48,6446.1 1351.47,6326.1 2061.55,6326.1 2129.01,6258.64 2129.01,6018.72 2421.93,5725.81 2421.93,4357.27 2239.52,4174.86 2036.22,4174.86 v3(2018.14,4192.94)
  L7-INT 2 w10: J4.2@731.41,6077.18 770.76,6077.18 843.36,6149.79 896.26,6149.79 944.28,6197.81 944.28,6559.45 993.21,6608.38 1162.61,6608.38 TP31.1@1278.73,6724.5
  L7-INT 2 w50: J4.4@631.41,6077.18 J4.2@731.41,6077.18
  Bottom Layer w50: J4.4@631.41,6077.18 J4.2@731.41,6077.18
ILIM_1: J6.2 J6.4 TP32.1 U2.8 | length 3937.7
  Top Layer w8: U2.8@1935.88,5210.96 1935.88,5171.6 v3(1954.63,5152.84)
  Top Layer w50: J6.4@667.98,6430.62 J6.2@767.98,6430.62
  L8-INT 3 w8: J6.2@767.98,6430.62 844.71,6353.9 1156.61,6353.9 1333.73,6176.77 1333.73,6086.28 1422.45,5997.56 2008.18,5997.56 v3(2216.09,5789.65)
  L7-INT 2 w8: v3(1954.63,5152.84) 1981.97,5125.5 2254.47,5125.5 2340.77,5211.8 2340.77,5664.97 v3(2216.09,5789.65)
  L9-INT 4 w8: J6.2@767.98,6430.62 840.8,6503.44 840.8,6580.46 1236.51,6976.17 TP32.1@1236.51,7074.5
  Bottom Layer w50: J6.4@667.98,6430.62 J6.2@767.98,6430.62 J6.2@772.53,6430.62
ILIM_2: J7.2 J7.4 TP33.1 U3.8 | length 4291.1
  Top Layer w50: J7.4@993.21,6430.62 J7.2@1093.21,6430.62
  L8-INT 3 w8: J7.2@1093.21,6430.62 1155.41,6430.62 1279.36,6306.67 2054.25,6306.67 2113.07,6247.86 2113.07,6008.06 2402.92,5718.2 2402.92,5264.11 2315.14,5176.33 2315.14,4963.9 2218.15,4866.91 2218.15,4579.29 2180.82,4541.95 v3(2028.6,4541.95)
  L9-INT 4 w8: J7.2@1093.21,6430.62 1350.77,6688.19 1350.77,6994.32 TP33.1@1430.95,7074.5
  Bottom Layer w8: U3.8@1935.88,4469.52 1935.88,4487.4 1959.91,4511.43 2012.44,4511.43 2028.6,4527.59 v3(2028.6,4541.95)
  Bottom Layer w50: J7.4@993.21,6430.62 J7.2@1093.21,6430.62
ILIM_3: J8.2 J8.4 TP34.1 U4.8 | length 4841.6
  Top Layer w8: U4.8@1935.18,3323.77 1935.18,3305.04 1948.88,3291.34 1977.79,3291.34 v3(2015.73,3253.4)
  Top Layer w20: J8.4@1636.63,6430.62 J8.4@1643.66,6430.62
  Top Layer w50: J8.4@1643.66,6430.62 J8.2@1743.66,6430.62
  L8-INT 3 w8: J8.2@1743.66,6430.62 1800.38,6373.9 2063.3,6373.9 2158.75,6278.45 2158.75,6273.4 2159.01,6273.14 2159.01,6034.98 2339.74,5854.26 2397.96,5854.26 2459.83,5792.39 2459.83,3439.81 2241.95,3221.93 2047.2,3221.93 v3(2015.73,3253.4)
  L7-INT 2 w8: J8.2@1743.66,6430.62 1916.53,6603.5 2001.84,6603.5 2098.73,6700.39 TP34.1@2098.73,6724.5
  Bottom Layer w50: J8.4@1643.66,6430.62 J8.2@1743.66,6430.62
ILIM_4: J9.2 J9.4 TP35.1 U5.8 | length 4944.2
  Top Layer w50: J9.4@1318.43,6430.62 J9.2@1418.43,6430.62
  L8-INT 3 w8: J9.2@1418.43,6430.62 1500.16,6348.9 2062.04,6348.9 2144.01,6266.93 2144.01,6028.77 2439.28,5733.5 2439.28,3635.07 2384.79,3580.57 2049.05,3580.57 v3(2029.95,3599.68)
  L7-INT 2 w8: J9.2@1418.43,6430.62 1588.59,6600.79 1770.02,6600.79 TP35.1@1893.73,6724.5
  Bottom Layer w8: U5.8@1935.18,3490.89 1935.18,3525.07 1982.5,3572.39 2002.66,3572.39 v3(2029.95,3599.68)
  Bottom Layer w50: J9.4@1318.43,6430.62 J9.2@1418.43,6430.62
ILIM_5: J10.2 J10.4 TP36.1 U6.8 | length 5565.2
  Top Layer w8: U6.8@1935.88,2378.37 1935.88,2348.21 v3(1949.69,2334.4)
  Top Layer w50: J10.4@1968.88,6430.62 J10.2@2068.88,6430.62
  L8-INT 3 w8: v3(1949.69,2334.4) 1990.14,2293.94 2294.25,2293.94 2479.28,2478.97 2479.28,5801.74 2408.26,5872.76 2342.99,5872.76 2174.28,6041.47 2174.28,6325.22 J10.2@2068.88,6430.62
  L7-INT 2 w8: J10.2@2068.88,6430.62 2160.79,6522.53 2160.79,6837.44 TP36.1@2098.73,6899.5
  Bottom Layer w50: J10.4@1968.88,6430.62 J10.2@2068.88,6430.62
IMON: CM1.2 J3.2 J3.4 RZ11.2 RZ18.2 RZ25.2 RZ32.2 RZ39.2 RZ46.2 TP20.1 | length 7358.5
  Top Layer w8: v3(1949.46,5023.9) RZ18.2@1949.46,5054.74
  Top Layer w10: v3(1926.37,2184.87) RZ46.2@1926.37,2216.11 ; RZ11.2@1995.23,4097.6 1995.23,4062.2 v3(2002.81,4054.62) ; v3(1999.97,3139) RZ32.2@1999.97,3167.28
  L8-INT 3 w8: J3.4@993.21,6080.62 J3.2@1093.21,6080.62 1341.38,5832.45 1341.38,5198.59 1435.56,5104.41 1868.94,5104.41 v3(1949.46,5023.9)
  L7-INT 2 w8: v3(1926.37,2184.87) 2230.3,2184.87 2439.28,2393.85 2439.28,2948.72 2331.61,3056.4 2082.57,3056.4 v3(1999.97,3139) 1999.97,3177.16 2036.71,3213.9 2240.82,3213.9 2309.28,3282.36 2309.28,3547.55 2250.18,3606.65 2090.79,3606.65 2042.74,3654.7 2005.21,3654.7 1991.91,3668.01 v3(1991.91,3712.3) 1991.91,4043.72 v3(2002.81,4054.62) 2045.79,4097.6 2252.98,4097.6 2309.7,4154.32 2309.7,4494.39 2180.37,4623.72 2077.51,4623.72 v3(2022.34,4678.9) 2022.34,4951.01 v3(1949.46,5023.9)
  L9-INT 4 w8: J3.4@993.21,6080.62 938.92,6134.91 938.92,6589.69 TP20.1@1073.73,6724.5
  Bottom Layer w10: RZ39.2@1991.91,3678.28 v3(1991.91,3712.3) ; CM1.2@1995.23,4097.6 1995.23,4062.2 v3(2002.81,4054.62) ; RZ25.2@2022.34,4638.87 v3(2022.34,4678.9)
  Bottom Layer w50: J3.4@993.21,6080.62 J3.2@1093.21,6080.62
IMON_0: RZ11.1 U1.7 | length 168.9
  Top Layer w7.87: U1.7@1920.13,4266.76 1920.13,4233.96 1944.61,4209.49 1971.63,4209.49 1995.23,4185.89 RZ11.1@1995.23,4144.84
IMON_1: RZ18.1 U2.7 | length 121.1
  Top Layer w8: U2.7@1920.13,5210.96 1920.13,5131.31 RZ18.1@1949.46,5101.99
IMON_2: RZ25.1 U3.7 | length 167.9
  Bottom Layer w8: U3.7@1920.13,4469.52 1920.13,4495.33 1955.23,4530.43 1961.18,4530.43 RZ25.1@2022.34,4591.62
IMON_3: RZ32.1 U4.7 | length 158.3
  Top Layer w8: U4.7@1919.43,3323.77 1919.43,3291.16 1936.85,3273.75 1963.58,3273.75 1999.97,3237.36 RZ32.1@1999.97,3214.52
IMON_4: RZ39.1 U5.7 | length 170.2
  Bottom Layer w8: U5.7@1919.43,3490.89 1919.43,3530.53 v3(1981.45,3592.55) 1991.91,3603.01 RZ39.1@1991.91,3631.03
IMON_5: RZ46.1 U6.7 | length 117.6
  Top Layer w8: U6.7@1920.13,2378.37 1920.13,2336.05 1926.37,2329.81 RZ46.1@1926.37,2263.36
IREF: CF1.1 R45.2 TP30.1 U1.9 U2.9 U3.9 U4.9 U5.9 U6.9 | length 8950.3
  Top Layer w8: TP30.1@653.17,7074.5 655.93,7077.26 CF1.1@655.93,7196.75 ; U2.9@1955.81,5216.13 1988.14,5216.13 v3(2005.87,5198.39)
  Top Layer w10: U6.9@1955.81,2383.54 1992.72,2383.54 v3(2005.76,2370.5) ; U4.9@1955.81,3327.73 1990.25,3327.73 2005.06,3312.92 v3(2005.06,3297.98) ; U1.9@1955.81,4271.93 1955.81,4251.02 1963.94,4242.89 v3(1994.32,4242.89)
  L8-INT 3 w8: TP30.1@653.17,7074.5 790,6937.67 790,6614.65 835.32,6569.33 835.32,6430.68 893.41,6372.59 1162.41,6372.59 1351.47,6183.52 1351.47,6104.58 1437.95,6018.1 2022.1,6018.1 2340.48,5699.73 2340.48,5296.79 2226.61,5182.92 2035.1,5182.92 2019.62,5198.39 v3(2005.87,5198.39) 1990.4,5182.92 1990.4,5064.94 2061.55,4993.79 2061.55,4630.25 1958.86,4527.55 1958.86,4479.61 1978.24,4460.24 1990.2,4460.24 v3(2012.41,4482.44) 2050.09,4520.12 2263.73,4520.12 2336.96,4446.89 2336.96,4350.76 2193.29,4207.09 2037.46,4207.09 2001.66,4242.89 v3(1994.32,4242.89) 1984.8,4233.37 1984.8,4141.91 2061.55,4065.15 2061.55,3673.8 2009.08,3621.33 2009.08,3582.05 v3(2029.95,3561.18)
  L7-INT 2 w8: v3(2005.76,2370.5) 2057.36,2318.9 2284.61,2318.9 2403.85,2438.13 2403.85,2859.15 2261.45,3001.55 2053.26,3001.55 1953.74,3101.08 1953.74,3201.47 1981.17,3228.9 1981.17,3274.08 v3(2005.06,3297.98) 2032.73,3297.98 2050.43,3280.27 2210.99,3280.27 2274.28,3343.57 2274.28,3525.35 2238.45,3561.18 v3(2029.95,3561.18)
  Bottom Layer w8: TP30.1@653.17,7074.5 655.93,7077.26 R45.2@655.93,7196.75 ; U5.9@1955.11,3485.73 1955.11,3522.37 1966.87,3534.13
  Bottom Layer w10: U3.9@1955.81,4464.35 1994.32,4464.35 v3(2012.41,4482.44) ; 1966.87,3534.13 1987.31,3554.57 2023.34,3554.57 v3(2029.95,3561.18)
ITIMER: J5.2 J5.4 J5.6 TP29.1 U1.6 | length 4163.5
  Top Layer w7.87: U1.6@1904.38,4266.76 1904.38,4223.75 1939.42,4188.72 v3(1963.94,4188.72)
  L7-INT 2 w10: TP29.1@663.73,6724.5 728.37,6789.14 1320.78,6789.14 1369.97,6739.95 1369.97,6179.73 J5.6@1451,6098.69 J5.4@1551,6098.69 J5.2@1651,6098.69
  L9-INT 4 w10: J5.6@1451,6098.69 1451,6009.13 1468.99,5991.14 1468.99,4249.19 1579.28,4138.9 1914.12,4138.9 v3(1963.94,4188.72)
MODE: TP39.1 U1.17 | length 3016.4
  Top Layer w8: U1.17@1904.38,4451.8 1904.38,4487.61 1939.35,4522.57 1984.18,4522.57 v3(2001.3,4539.69)
  L9-INT 4 w8: v3(2001.3,4539.69) 2001.3,4573.55 2402.92,4975.18 2402.92,5717.6 2167.64,5952.88 2167.64,6921.14 TP39.1@2014.28,7074.5
MODE_1: RM1.1 U2.17 | length 150.9
  Top Layer w8: U2.17@1904.38,5396 1904.38,5434.39 1969.88,5499.89 RM1.1@1969.88,5519.8
  other v3: 1961.47,5491.47
MODE_2: RM2.1 U3.17 | length 157.2
  Bottom Layer w7.87: U3.17@1904.38,4284.48 1904.38,4212.34 1946.84,4169.88 RM2.1@1946.84,4144.84
MODE_3: RM3.1 U4.17 | length 158.8
  Top Layer w8: U4.17@1903.68,3508.81 1903.68,3542.79 RM3.1@1991.91,3631.03
MODE_4: RM4.1 U5.17 | length 129
  Bottom Layer w8: U5.17@1903.68,3305.85 1903.68,3275.93 1918.33,3261.28 1946.69,3261.28 v3(1954.58,3253.4) RM4.1@1954.58,3214.52
MODE_5: RM5.1 U6.17 | length 148.3
  Top Layer w8: U6.17@1904.38,2563.41 1904.38,2599.39 1966.85,2661.85 RM5.1@1966.85,2685.83
  other v3: 1958.76,2653.77
NetC2_1: C2.1 RZ3.1 U9.1 | length 127.1
  Top Layer w10: U9.1@3133.01,7552 3164.53,7552 C2.1@3182.57,7533.96
  Top Layer w15: C2.1@3182.57,7533.96 3187.97,7533.96 3226.24,7572.23 RZ3.1@3236.8,7572.23
NetC2_2: C2.2 RZ1.1 U9.8 | length 133.1
  Top Layer w10: U9.8@3133.01,7449.64 3161.24,7449.64 C2.2@3182.57,7470.97
  Top Layer w15: C2.2@3182.57,7470.97 3184.89,7470.97 3232,7423.85 RZ1.1@3237.75,7423.85
NetC3_1: C3.1 RZ2.1 TP5.1 | length 1000.7
  Top Layer w20: TP5.1@2208.73,7074.5 2208.73,7126.31 2360.2,7277.78 2509.33,7277.78 2674.02,7442.48 2919.28,7442.48 2938.89,7422.88 C3.1@2938.89,7398.92 RZ2.1@2994.57,7398.92
NetC18_2: C18.2 R40.1 SW3.1 SW3.2 U16.B1 | length 433.2
  Top Layer w10: R40.1@1161.25,7351.34 1164.85,7354.94 1164.85,7397.98 1189.04,7422.17 U16.B1@1189.04,7430.09
  Top Layer w20: R40.1@1161.25,7351.34 C18.2@1161.25,7290.26 1161.25,7281.59 1192.03,7250.8 1291.55,7250.8 SW3.1@1294.48,7253.73 SW3.2@1294.48,7379.72
NetC27_1: C27.1 D1.3 R46.2 R49.2 | length 221.9
  Top Layer w20: C27.1@374.02,6190.3 354.41,6170.7 v5(354.41,6148) 376.51,6125.9 R49.2@414.02,6125.9
  Bottom Layer w20: v5(354.41,6148) R46.2@354.41,6190.01 411.48,6190.01 D1.3@414.02,6192.55
NetC28_1: C28.1 J5.1 | length 108.4
  Bottom Layer w20: J5.1@1651,6198.69 C28.1@1651,6307.12
NetC29_1: C29.1 J5.5 | length 108.4
  Bottom Layer w20: J5.5@1451,6198.69 C29.1@1451,6307.12
NetC30_1: C30.1 J5.3 | length 118.5
  Bottom Layer w20: J5.3@1551,6198.69 C30.1@1551,6317.2
NetCD1_1: CD1.1 J2.1 | length 80.2
  Bottom Layer w20: CD1.1@2057.47,6277.02 2057.47,6203.27 J2.1@2062.04,6198.69
NetCD2_1: CD2.1 J2.5 | length 82.3
  Bottom Layer w20: J2.5@1862.04,6198.69 1863.11,6199.76 CD2.1@1863.11,6280.53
